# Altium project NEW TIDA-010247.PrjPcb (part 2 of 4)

## Sheet AFE and External Balancing.SchDoc
size A2; Date: Not shown in title block; ApprovedBy: Not shown in title block; CheckedBy: Not shown in title block; Author: Not shown in title block; CompanyName: Not shown in title block; Engineer: Not shown in title block; Organization: Not shown in title block; Address1: Not shown in title block; Address2: Not shown in title block; Address3: Not shown in title block; Address4: Not shown in title block; DocumentNumber: 1; Revision: Use project parameter SCH_Rev; SheetNumber: 3; SheetTotal: 10; PageSetup: Record=PageOptions¦CenterHorizontal=True¦CenterVertical=True¦PrintScale=0.69¦XCorrection=1.00¦YCorrection=1.00¦PrintKind=0¦BorderSize=5000000¦LeftOffset=0¦BottomOffset=0¦Orientation=2¦PaperLength=1000¦PaperWidth=1000¦Scale=100¦PaperSource=15¦PrintQuality=600¦MediaType=1¦DitherType=10¦PaperKind=Letter¦PrintScaleMode=1
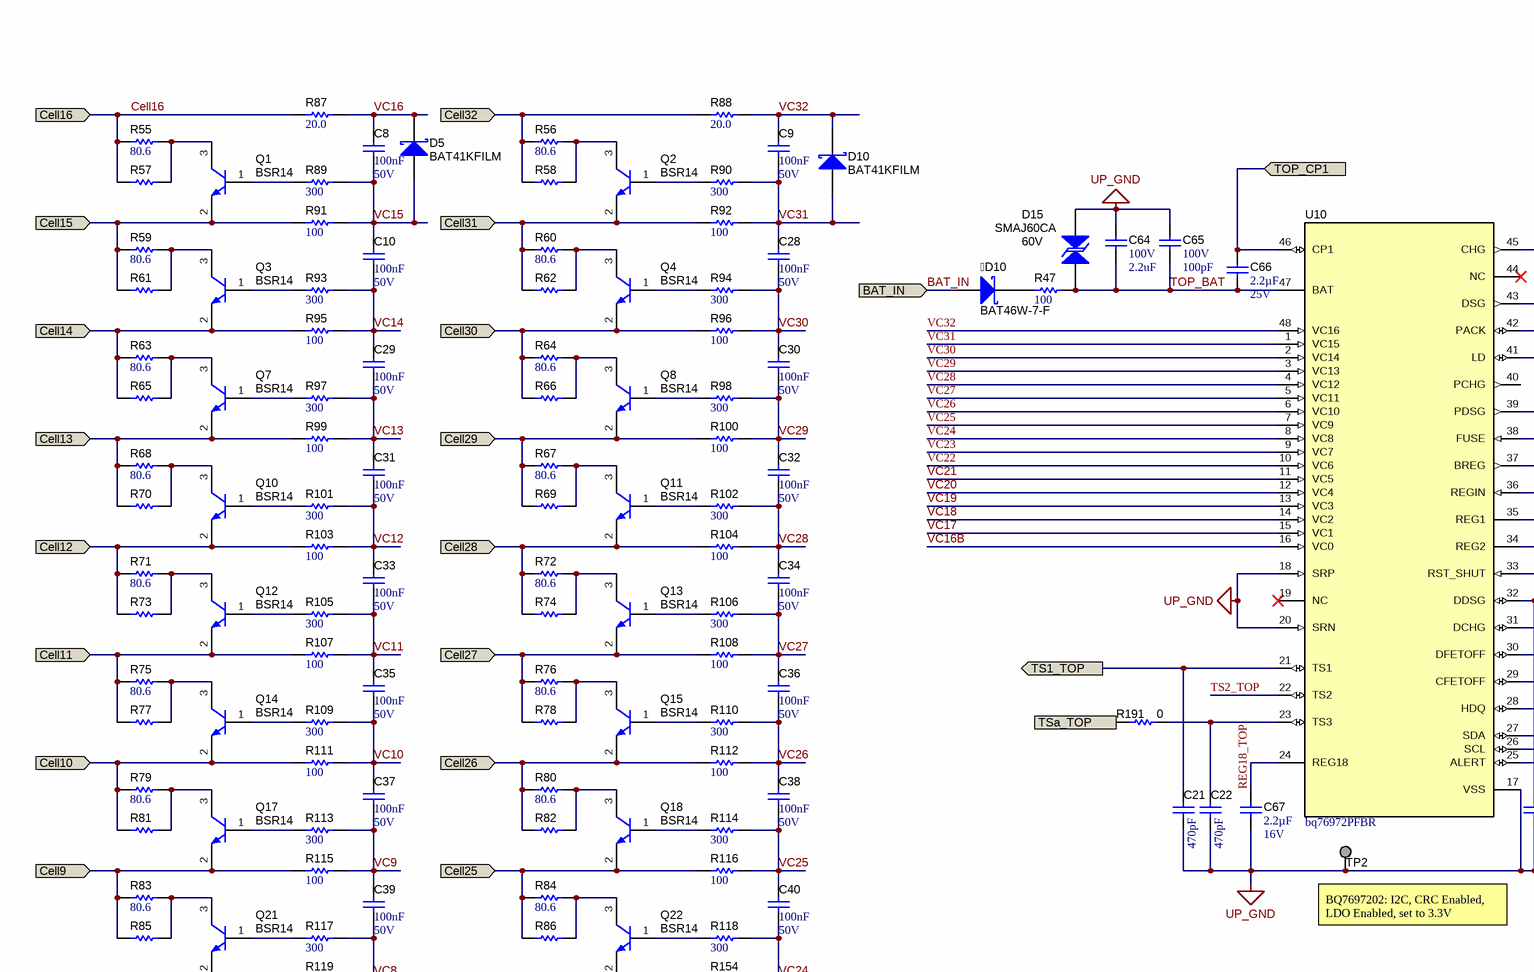
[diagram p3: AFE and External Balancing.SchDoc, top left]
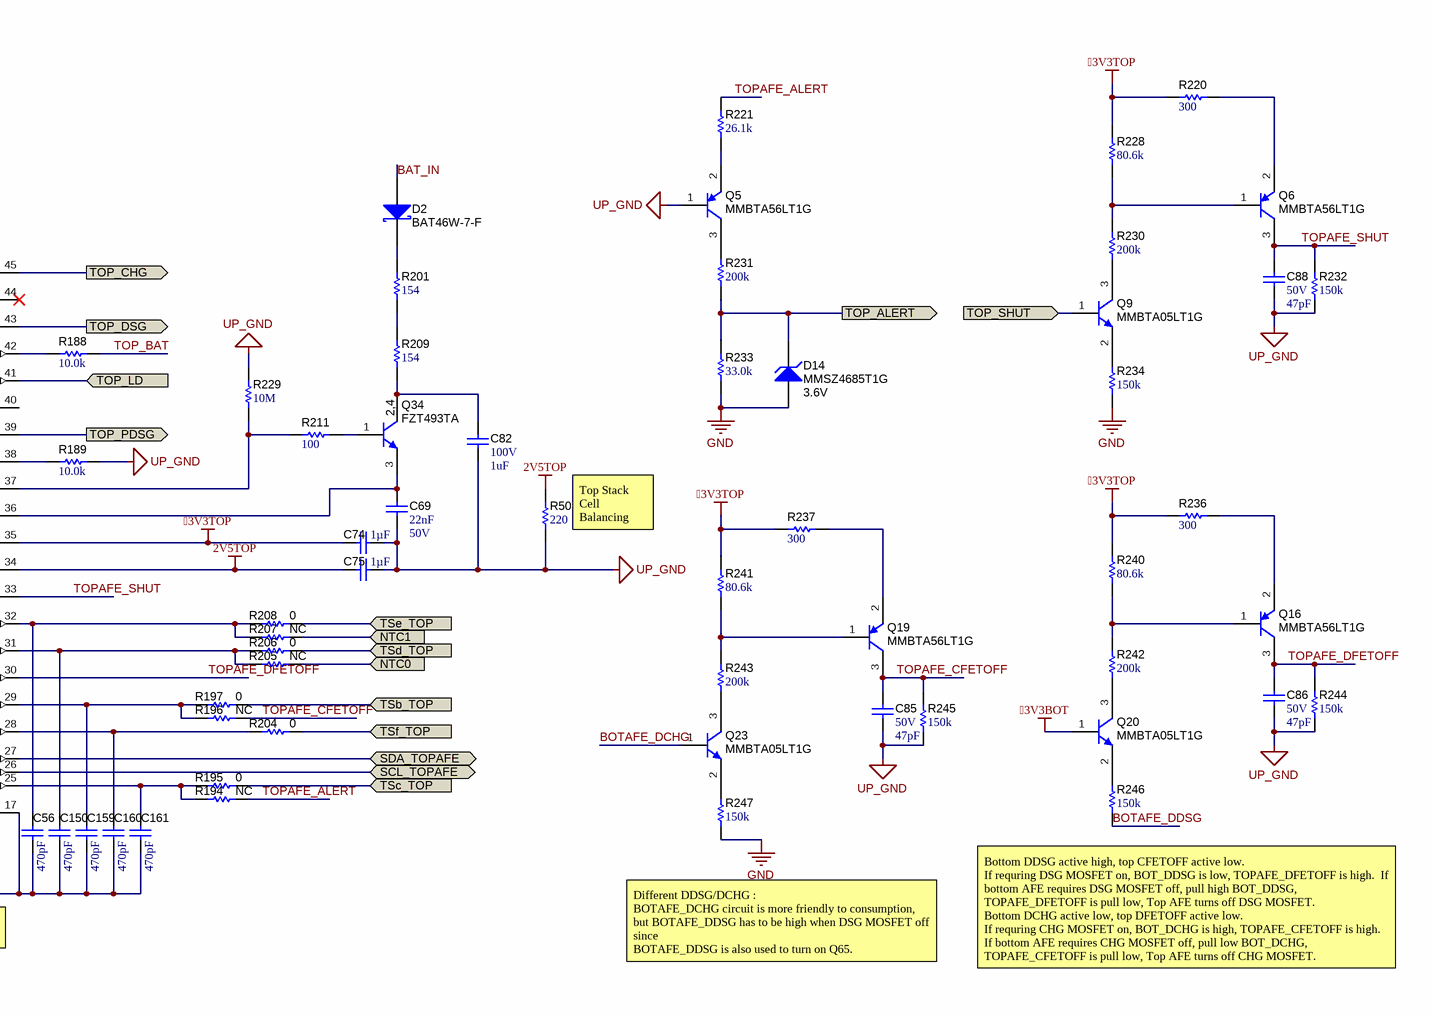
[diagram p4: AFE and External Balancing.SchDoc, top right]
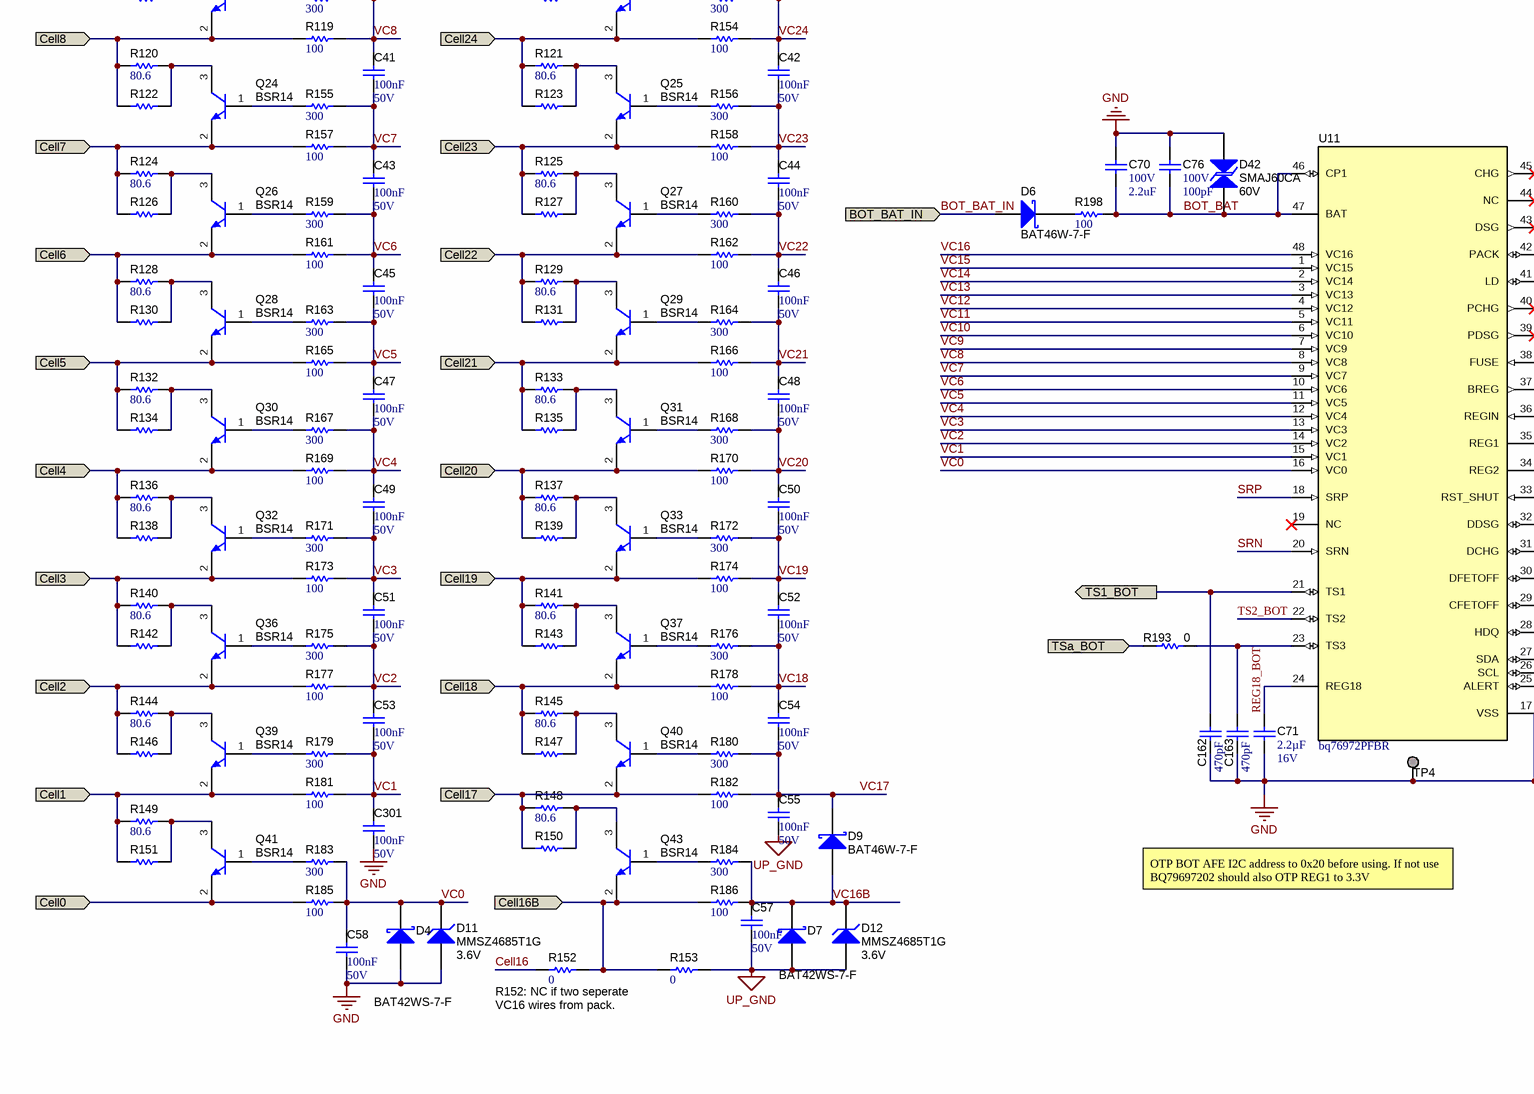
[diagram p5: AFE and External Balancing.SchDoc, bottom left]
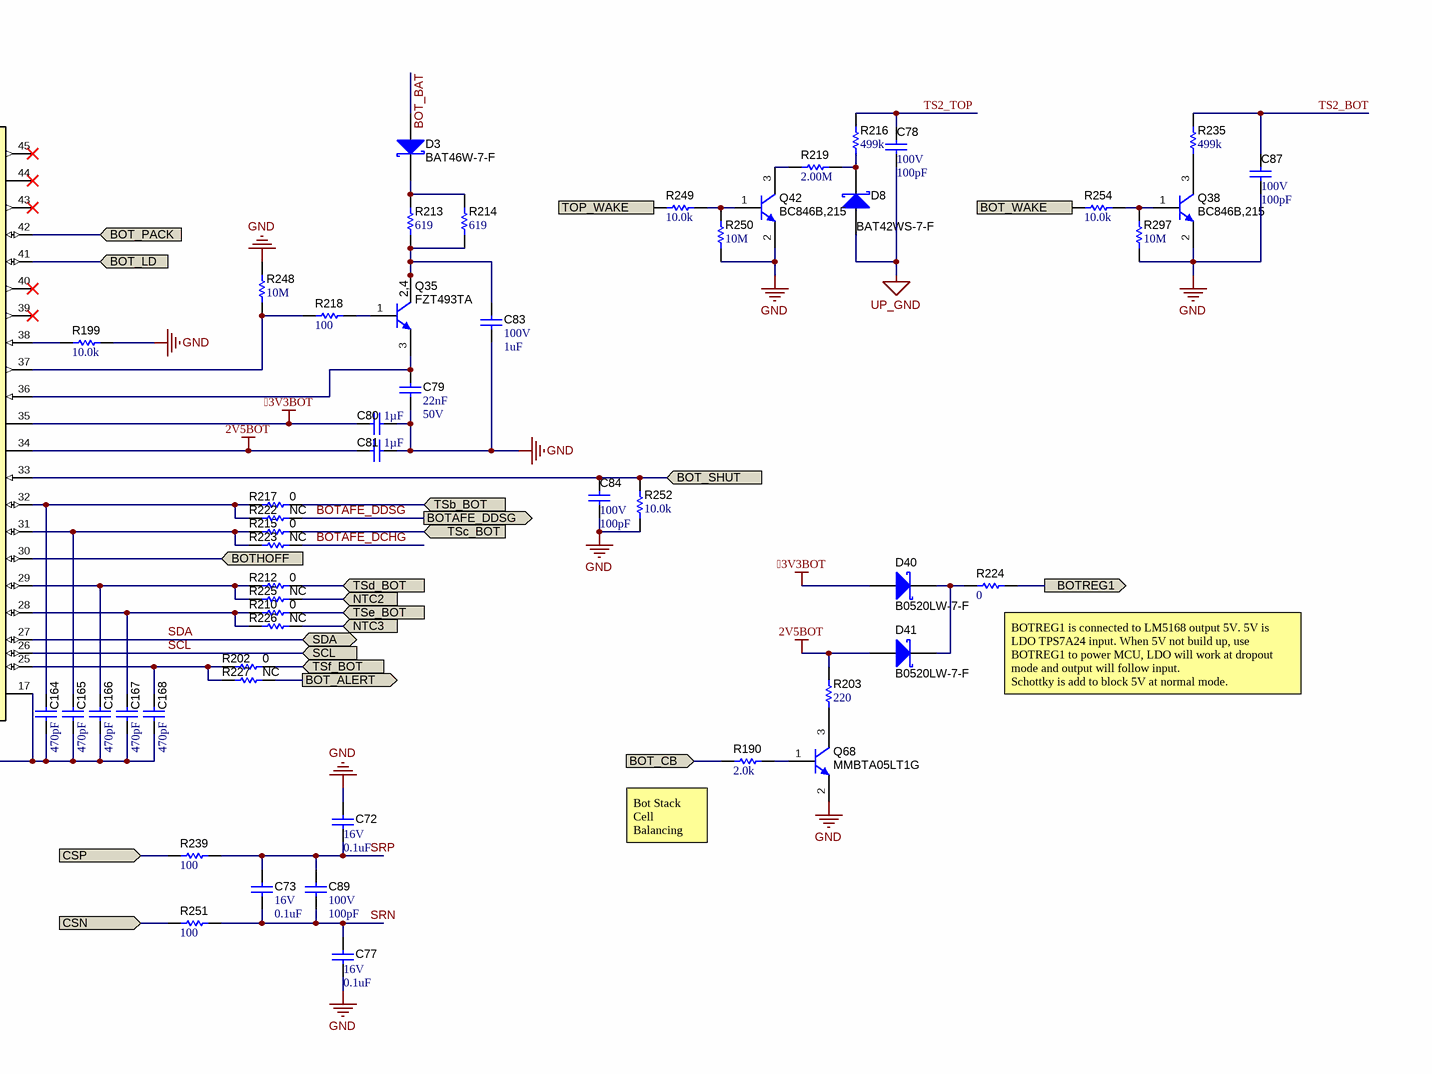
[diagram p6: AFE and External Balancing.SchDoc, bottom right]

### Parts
D10  BAT46W-7-F  [SOD-123]
C8  Cap_F: 100nF  VDC_V: 50V  [0603]  (hidden comment: GRM188R71H104KA93D)
C9  Cap_F: 100nF  VDC_V: 50V  [0603]  (hidden comment: GRM188R71H104KA93D)
C10  Cap_F: 100nF  VDC_V: 50V  [0603]  (hidden comment: GRM188R71H104KA93D)
C21  ValueDisplayed: 470pF  [0201]  (hidden comment: GRM033R71C471KA01D)  (no BOM)
C22  ValueDisplayed: 470pF  [0201]  (hidden comment: GRM033R71C471KA01D)
C28  Cap_F: 100nF  VDC_V: 50V  [0603]  (hidden comment: GRM188R71H104KA93D)
C29  Cap_F: 100nF  VDC_V: 50V  [0603]  (hidden comment: GRM188R71H104KA93D)
C30  Cap_F: 100nF  VDC_V: 50V  [0603]  (hidden comment: GRM188R71H104KA93D)
C31  Cap_F: 100nF  VDC_V: 50V  [0603]  (hidden comment: GRM188R71H104KA93D)
C32  Cap_F: 100nF  VDC_V: 50V  [0603]  (hidden comment: GRM188R71H104KA93D)
C33  Cap_F: 100nF  VDC_V: 50V  [0603]  (hidden comment: GRM188R71H104KA93D)
C34  Cap_F: 100nF  VDC_V: 50V  [0603]  (hidden comment: GRM188R71H104KA93D)
C35  Cap_F: 100nF  VDC_V: 50V  [0603]  (hidden comment: GRM188R71H104KA93D)
C36  Cap_F: 100nF  VDC_V: 50V  [0603]  (hidden comment: GRM188R71H104KA93D)
C37  Cap_F: 100nF  VDC_V: 50V  [0603]  (hidden comment: GRM188R71H104KA93D)
C38  Cap_F: 100nF  VDC_V: 50V  [0603]  (hidden comment: GRM188R71H104KA93D)
C39  Cap_F: 100nF  VDC_V: 50V  [0603]  (hidden comment: GRM188R71H104KA93D)
C40  Cap_F: 100nF  VDC_V: 50V  [0603]  (hidden comment: GRM188R71H104KA93D)
C41  Cap_F: 100nF  VDC_V: 50V  [0603]  (hidden comment: GRM188R71H104KA93D)
C42  Cap_F: 100nF  VDC_V: 50V  [0603]  (hidden comment: GRM188R71H104KA93D)
C43  Cap_F: 100nF  VDC_V: 50V  [0603]  (hidden comment: GRM188R71H104KA93D)
C44  Cap_F: 100nF  VDC_V: 50V  [0603]  (hidden comment: GRM188R71H104KA93D)
C45  Cap_F: 100nF  VDC_V: 50V  [0603]  (hidden comment: GRM188R71H104KA93D)
C46  Cap_F: 100nF  VDC_V: 50V  [0603]  (hidden comment: GRM188R71H104KA93D)
C47  Cap_F: 100nF  VDC_V: 50V  [0603]  (hidden comment: GRM188R71H104KA93D)
C48  Cap_F: 100nF  VDC_V: 50V  [0603]  (hidden comment: GRM188R71H104KA93D)
C49  Cap_F: 100nF  VDC_V: 50V  [0603]  (hidden comment: GRM188R71H104KA93D)
C50  Cap_F: 100nF  VDC_V: 50V  [0603]  (hidden comment: GRM188R71H104KA93D)
C51  Cap_F: 100nF  VDC_V: 50V  [0603]  (hidden comment: GRM188R71H104KA93D)
C52  Cap_F: 100nF  VDC_V: 50V  [0603]  (hidden comment: GRM188R71H104KA93D)
C53  Cap_F: 100nF  VDC_V: 50V  [0603]  (hidden comment: GRM188R71H104KA93D)
C54  Cap_F: 100nF  VDC_V: 50V  [0603]  (hidden comment: GRM188R71H104KA93D)
C55  Cap_F: 100nF  VDC_V: 50V  [0603]  (hidden comment: GRM188R71H104KA93D)
C56  ValueDisplayed: 470pF  [0201]  (hidden comment: GRM033R71C471KA01D)
C57  Cap_F: 100nF  VDC_V: 50V  [0603]  (hidden comment: GRM188R71H104KA93D)
C58  Cap_F: 100nF  VDC_V: 50V  [0603]  (hidden comment: GRM188R71H104KA93D)
C64  VDC_V: 100V  ValueDisplayed: 2.2uF  [1206_190]  (hidden comment: GRM31CR72A225KA73L)
C65  VDC_V: 100V  ValueDisplayed: 100pF  [0603]  (hidden comment: GRM1885C2A101JA01D)
C66  Cap_F: 2.2µF  VDC_V: 25V  [0805_HV]  (hidden comment: GRM21BR71E225KA73L)
C67  Cap_F: 2.2µF  VDC_V: 16V  [0603]  (hidden comment: EMK107BB7225MA-T)
C69  Cap_F: 22nF  VDC_V: 50V  [0603]  (hidden comment: GRM188R71H223KA01D)
C70  VDC_V: 100V  ValueDisplayed: 2.2uF  [1206_190]  (hidden comment: GRM31CR72A225KA73L)
C71  Cap_F: 2.2µF  VDC_V: 16V  [0603]  (hidden comment: EMK107BB7225MA-T)
C72  VDC_V: 16V  ValueDisplayed: 0.1uF  [0603]  (hidden comment: GRM188R61C104KA01D)
C73  VDC_V: 16V  ValueDisplayed: 0.1uF  [0603]  (hidden comment: GRM188R61C104KA01D)
C74  Cap_F: 1µF  [0603]  (hidden comment: GCM188R71C105KA64D)
C75  Cap_F: 1µF  [0603]  (hidden comment: GCM188R71C105KA64D)
C76  VDC_V: 100V  ValueDisplayed: 100pF  [0603]  (hidden comment: GRM1885C2A101JA01D)
C77  VDC_V: 16V  ValueDisplayed: 0.1uF  [0603]  (hidden comment: GRM188R61C104KA01D)
C78  VDC_V: 100V  ValueDisplayed: 100pF  [0603]  (hidden comment: GRM1885C2A101JA01D)
C79  Cap_F: 22nF  VDC_V: 50V  [0603]  (hidden comment: GRM188R71H223KA01D)
C80  Cap_F: 1µF  [0603]  (hidden comment: GCM188R71C105KA64D)
C81  Cap_F: 1µF  [0603]  (hidden comment: GCM188R71C105KA64D)
C82  VDC_V: 100V  ValueDisplayed: 1uF  [1206_180]  (hidden comment: C3216X7R2A105K160AA)
C83  VDC_V: 100V  ValueDisplayed: 1uF  [1206_180]  (hidden comment: C3216X7R2A105K160AA)
C84  VDC_V: 100V  ValueDisplayed: 100pF  [0603]  (hidden comment: GRM1885C2A101JA01D)
C85  VDC_V: 50V  ValueDisplayed: 47pF  [0603]  (hidden comment: GRM1885C1H470JA01D)
C86  VDC_V: 50V  ValueDisplayed: 47pF  [0603]  (hidden comment: GRM1885C1H470JA01D)
C87  VDC_V: 100V  ValueDisplayed: 100pF  [0603]  (hidden comment: GRM1885C2A101JA01D)
C88  VDC_V: 50V  ValueDisplayed: 47pF  [0603]  (hidden comment: GRM1885C1H470JA01D)
C89  VDC_V: 100V  ValueDisplayed: 100pF  [0603]  (hidden comment: GRM1885C2A101JA01D)
C150  ValueDisplayed: 470pF  [0201]  (hidden comment: GRM033R71C471KA01D)
C159  ValueDisplayed: 470pF  [0201]  (hidden comment: GRM033R71C471KA01D)
C160  ValueDisplayed: 470pF  [0201]  (hidden comment: GRM033R71C471KA01D)
C161  ValueDisplayed: 470pF  [0201]  (hidden comment: GRM033R71C471KA01D)
C162  ValueDisplayed: 470pF  [0201]  (hidden comment: GRM033R71C471KA01D)  (no BOM)
C163  ValueDisplayed: 470pF  [0201]  (hidden comment: GRM033R71C471KA01D)
C164  ValueDisplayed: 470pF  [0201]  (hidden comment: GRM033R71C471KA01D)
C165  ValueDisplayed: 470pF  [0201]  (hidden comment: GRM033R71C471KA01D)
C166  ValueDisplayed: 470pF  [0201]  (hidden comment: GRM033R71C471KA01D)
C167  ValueDisplayed: 470pF  [0201]  (hidden comment: GRM033R71C471KA01D)
C168  ValueDisplayed: 470pF  [0201]  (hidden comment: GRM033R71C471KA01D)
C301  Cap_F: 100nF  VDC_V: 50V  [0603]  (hidden comment: GRM188R71H104KA93D)
D2  BAT46W-7-F  [SOD-123]
D3  BAT46W-7-F  [SOD-123]
D4  BAT42WS-7-F  [SOD-323]
D5  BAT41KFILM  [SOD-523]
D6  BAT46W-7-F  [SOD-123]
D7  BAT42WS-7-F  [SOD-323]
D8  BAT42WS-7-F  [SOD-123]
D9  BAT46W-7-F  [SOD-123]
D10  BAT41KFILM  [SOD-523]
D11  MMSZ4685T1G  value 3.6V  [SOD-123]
D12  MMSZ4685T1G  value 3.6V  [SOD-123]
D14  MMSZ4685T1G  value 3.6V  [SOD-123]
D15  SMAJ60CA  value 60V  [SMA_Bi]
D40  B0520LW-7-F  [SOD-123]
D41  B0520LW-7-F  [SOD-123]  (no BOM)
D42  SMAJ60CA  value 60V  [SMA_Bi]
Q1  BSR14  [SOT-23]
Q2  BSR14  [SOT-23]
Q3  BSR14  [SOT-23]
Q4  BSR14  [SOT-23]
Q5  MMBTA56LT1G  [SOT-23]
Q6  MMBTA56LT1G  [SOT-23]
Q7  BSR14  [SOT-23]
Q8  BSR14  [SOT-23]
Q9  MMBTA05LT1G  [SOT-23]
Q10  BSR14  [SOT-23]
Q11  BSR14  [SOT-23]
Q12  BSR14  [SOT-23]
Q13  BSR14  [SOT-23]
Q14  BSR14  [SOT-23]
Q15  BSR14  [SOT-23]
Q16  MMBTA56LT1G  [SOT-23]
Q17  BSR14  [SOT-23]
Q18  BSR14  [SOT-23]
Q19  MMBTA56LT1G  [SOT-23]
Q20  MMBTA05LT1G  [SOT-23]
Q21  BSR14  [SOT-23]
Q22  BSR14  [SOT-23]
Q23  MMBTA05LT1G  [SOT-23]
Q24  BSR14  [SOT-23]
Q25  BSR14  [SOT-23]
Q26  BSR14  [SOT-23]
Q27  BSR14  [SOT-23]
Q28  BSR14  [SOT-23]
Q29  BSR14  [SOT-23]
Q30  BSR14  [SOT-23]
Q31  BSR14  [SOT-23]
Q32  BSR14  [SOT-23]
Q33  BSR14  [SOT-23]
Q34  FZT493TA  [SOT-223]
Q35  FZT493TA  [SOT-223]
Q36  BSR14  [SOT-23]
Q37  BSR14  [SOT-23]
Q38  BC846B,215  [SOT-23]
Q39  BSR14  [SOT-23]
Q40  BSR14  [SOT-23]
Q41  BSR14  [SOT-23]
Q42  BC846B,215  [SOT-23]
Q43  BSR14  [SOT-23]
Q68  MMBTA05LT1G  [SOT-23]
R47  ValueDisplayed: 100  [0603]  (hidden comment: CRCW0603100RFKEA)
R50  ValueDisplayed: 220  [1210]  (hidden comment: RC1210FR-07220RL)  (no BOM)
R55  ValueDisplayed: 80.6  [1206]  (hidden comment: CRCW120680R6FKEA)
R56  ValueDisplayed: 80.6  [1206]  (hidden comment: CRCW120680R6FKEA)
R57  CRCW120680R6FKEA  [1206]  (value not drawn)
R58  CRCW120680R6FKEA  [1206]  (value not drawn)
R59  ValueDisplayed: 80.6  [1206]  (hidden comment: CRCW120680R6FKEA)
R60  ValueDisplayed: 80.6  [1206]  (hidden comment: CRCW120680R6FKEA)
R61  CRCW120680R6FKEA  [1206]  (value not drawn)
R62  CRCW120680R6FKEA  [1206]  (value not drawn)
R63  ValueDisplayed: 80.6  [1206]  (hidden comment: CRCW120680R6FKEA)
R64  ValueDisplayed: 80.6  [1206]  (hidden comment: CRCW120680R6FKEA)
R65  CRCW120680R6FKEA  [1206]  (value not drawn)
R66  CRCW120680R6FKEA  [1206]  (value not drawn)
R67  ValueDisplayed: 80.6  [1206]  (hidden comment: CRCW120680R6FKEA)
R68  ValueDisplayed: 80.6  [1206]  (hidden comment: CRCW120680R6FKEA)
R69  CRCW120680R6FKEA  [1206]  (value not drawn)
R70  CRCW120680R6FKEA  [1206]  (value not drawn)
R71  ValueDisplayed: 80.6  [1206]  (hidden comment: CRCW120680R6FKEA)
R72  ValueDisplayed: 80.6  [1206]  (hidden comment: CRCW120680R6FKEA)
R73  CRCW120680R6FKEA  [1206]  (value not drawn)
R74  CRCW120680R6FKEA  [1206]  (value not drawn)
R75  ValueDisplayed: 80.6  [1206]  (hidden comment: CRCW120680R6FKEA)
R76  ValueDisplayed: 80.6  [1206]  (hidden comment: CRCW120680R6FKEA)
R77  CRCW120680R6FKEA  [1206]  (value not drawn)
R78  CRCW120680R6FKEA  [1206]  (value not drawn)
R79  ValueDisplayed: 80.6  [1206]  (hidden comment: CRCW120680R6FKEA)
R80  ValueDisplayed: 80.6  [1206]  (hidden comment: CRCW120680R6FKEA)
R81  CRCW120680R6FKEA  [1206]  (value not drawn)
R82  CRCW120680R6FKEA  [1206]  (value not drawn)
R83  ValueDisplayed: 80.6  [1206]  (hidden comment: CRCW120680R6FKEA)
R84  ValueDisplayed: 80.6  [1206]  (hidden comment: CRCW120680R6FKEA)
R85  CRCW120680R6FKEA  [1206]  (value not drawn)
R86  CRCW120680R6FKEA  [1206]  (value not drawn)
R87  ValueDisplayed: 20.0  [0603]  (hidden comment: CRCW060320R0FKEA)
R88  ValueDisplayed: 20.0  [0603]  (hidden comment: CRCW060320R0FKEA)
R89  ValueDisplayed: 300  [0603]  (hidden comment: CRCW0603300RJNEA)
R90  ValueDisplayed: 300  [0603]  (hidden comment: CRCW0603300RJNEA)
R91  ValueDisplayed: 100  [0603]  (hidden comment: CRCW0603100RFKEA)
R92  ValueDisplayed: 100  [0603]  (hidden comment: CRCW0603100RFKEA)
R93  ValueDisplayed: 300  [0603]  (hidden comment: CRCW0603300RJNEA)
R94  ValueDisplayed: 300  [0603]  (hidden comment: CRCW0603300RJNEA)
R95  ValueDisplayed: 100  [0603]  (hidden comment: CRCW0603100RFKEA)
R96  ValueDisplayed: 100  [0603]  (hidden comment: CRCW0603100RFKEA)
R97  ValueDisplayed: 300  [0603]  (hidden comment: CRCW0603300RJNEA)
R98  ValueDisplayed: 300  [0603]  (hidden comment: CRCW0603300RJNEA)
R99  ValueDisplayed: 100  [0603]  (hidden comment: CRCW0603100RFKEA)
R100  ValueDisplayed: 100  [0603]  (hidden comment: CRCW0603100RFKEA)
R101  ValueDisplayed: 300  [0603]  (hidden comment: CRCW0603300RJNEA)
R102  ValueDisplayed: 300  [0603]  (hidden comment: CRCW0603300RJNEA)
R103  ValueDisplayed: 100  [0603]  (hidden comment: CRCW0603100RFKEA)
R104  ValueDisplayed: 100  [0603]  (hidden comment: CRCW0603100RFKEA)
R105  ValueDisplayed: 300  [0603]  (hidden comment: CRCW0603300RJNEA)
R106  ValueDisplayed: 300  [0603]  (hidden comment: CRCW0603300RJNEA)
R107  ValueDisplayed: 100  [0603]  (hidden comment: CRCW0603100RFKEA)
R108  ValueDisplayed: 100  [0603]  (hidden comment: CRCW0603100RFKEA)
R109  ValueDisplayed: 300  [0603]  (hidden comment: CRCW0603300RJNEA)
R110  ValueDisplayed: 300  [0603]  (hidden comment: CRCW0603300RJNEA)
R111  ValueDisplayed: 100  [0603]  (hidden comment: CRCW0603100RFKEA)
R112  ValueDisplayed: 100  [0603]  (hidden comment: CRCW0603100RFKEA)
R113  ValueDisplayed: 300  [0603]  (hidden comment: CRCW0603300RJNEA)
R114  ValueDisplayed: 300  [0603]  (hidden comment: CRCW0603300RJNEA)
R115  ValueDisplayed: 100  [0603]  (hidden comment: CRCW0603100RFKEA)
R116  ValueDisplayed: 100  [0603]  (hidden comment: CRCW0603100RFKEA)
R117  ValueDisplayed: 300  [0603]  (hidden comment: CRCW0603300RJNEA)
R118  ValueDisplayed: 300  [0603]  (hidden comment: CRCW0603300RJNEA)
R119  ValueDisplayed: 100  [0603]  (hidden comment: CRCW0603100RFKEA)
R120  ValueDisplayed: 80.6  [1206]  (hidden comment: CRCW120680R6FKEA)
R121  ValueDisplayed: 80.6  [1206]  (hidden comment: CRCW120680R6FKEA)
R122  CRCW120680R6FKEA  [1206]  (value not drawn)
R123  CRCW120680R6FKEA  [1206]  (value not drawn)
R124  ValueDisplayed: 80.6  [1206]  (hidden comment: CRCW120680R6FKEA)
R125  ValueDisplayed: 80.6  [1206]  (hidden comment: CRCW120680R6FKEA)
R126  CRCW120680R6FKEA  [1206]  (value not drawn)
R127  CRCW120680R6FKEA  [1206]  (value not drawn)
R128  ValueDisplayed: 80.6  [1206]  (hidden comment: CRCW120680R6FKEA)
R129  ValueDisplayed: 80.6  [1206]  (hidden comment: CRCW120680R6FKEA)
R130  CRCW120680R6FKEA  [1206]  (value not drawn)
R131  CRCW120680R6FKEA  [1206]  (value not drawn)
R132  ValueDisplayed: 80.6  [1206]  (hidden comment: CRCW120680R6FKEA)
R133  ValueDisplayed: 80.6  [1206]  (hidden comment: CRCW120680R6FKEA)
R134  CRCW120680R6FKEA  [1206]  (value not drawn)
R135  CRCW120680R6FKEA  [1206]  (value not drawn)
R136  ValueDisplayed: 80.6  [1206]  (hidden comment: CRCW120680R6FKEA)
R137  ValueDisplayed: 80.6  [1206]  (hidden comment: CRCW120680R6FKEA)
R138  CRCW120680R6FKEA  [1206]  (value not drawn)
R139  CRCW120680R6FKEA  [1206]  (value not drawn)
R140  ValueDisplayed: 80.6  [1206]  (hidden comment: CRCW120680R6FKEA)
R141  ValueDisplayed: 80.6  [1206]  (hidden comment: CRCW120680R6FKEA)
R142  CRCW120680R6FKEA  [1206]  (value not drawn)
R143  CRCW120680R6FKEA  [1206]  (value not drawn)
R144  ValueDisplayed: 80.6  [1206]  (hidden comment: CRCW120680R6FKEA)
R145  ValueDisplayed: 80.6  [1206]  (hidden comment: CRCW120680R6FKEA)
R146  CRCW120680R6FKEA  [1206]  (value not drawn)
R147  CRCW120680R6FKEA  [1206]  (value not drawn)
R148  ValueDisplayed: 80.6  [1206]  (hidden comment: CRCW120680R6FKEA)
R149  ValueDisplayed: 80.6  [1206]  (hidden comment: CRCW120680R6FKEA)
R150  CRCW120680R6FKEA  [1206]  (value not drawn)
R151  CRCW120680R6FKEA  [1206]  (value not drawn)
R152  ValueDisplayed: 0  [0603]  (hidden comment: CRCW06030000Z0EA)
R153  ValueDisplayed: 0  [0603]  (hidden comment: CRCW06030000Z0EA)
R154  ValueDisplayed: 100  [0603]  (hidden comment: CRCW0603100RFKEA)
R155  ValueDisplayed: 300  [0603]  (hidden comment: CRCW0603300RJNEA)
R156  ValueDisplayed: 300  [0603]  (hidden comment: CRCW0603300RJNEA)
R157  ValueDisplayed: 100  [0603]  (hidden comment: CRCW0603100RFKEA)
R158  ValueDisplayed: 100  [0603]  (hidden comment: CRCW0603100RFKEA)
R159  ValueDisplayed: 300  [0603]  (hidden comment: CRCW0603300RJNEA)
R160  ValueDisplayed: 300  [0603]  (hidden comment: CRCW0603300RJNEA)
R161  ValueDisplayed: 100  [0603]  (hidden comment: CRCW0603100RFKEA)
R162  ValueDisplayed: 100  [0603]  (hidden comment: CRCW0603100RFKEA)
R163  ValueDisplayed: 300  [0603]  (hidden comment: CRCW0603300RJNEA)
R164  ValueDisplayed: 300  [0603]  (hidden comment: CRCW0603300RJNEA)
R165  ValueDisplayed: 100  [0603]  (hidden comment: CRCW0603100RFKEA)
R166  ValueDisplayed: 100  [0603]  (hidden comment: CRCW0603100RFKEA)
R167  ValueDisplayed: 300  [0603]  (hidden comment: CRCW0603300RJNEA)
R168  ValueDisplayed: 300  [0603]  (hidden comment: CRCW0603300RJNEA)
R169  ValueDisplayed: 100  [0603]  (hidden comment: CRCW0603100RFKEA)
R170  ValueDisplayed: 100  [0603]  (hidden comment: CRCW0603100RFKEA)
R171  ValueDisplayed: 300  [0603]  (hidden comment: CRCW0603300RJNEA)
R172  ValueDisplayed: 300  [0603]  (hidden comment: CRCW0603300RJNEA)
R173  ValueDisplayed: 100  [0603]  (hidden comment: CRCW0603100RFKEA)
R174  ValueDisplayed: 100  [0603]  (hidden comment: CRCW0603100RFKEA)
R175  ValueDisplayed: 300  [0603]  (hidden comment: CRCW0603300RJNEA)
R176  ValueDisplayed: 300  [0603]  (hidden comment: CRCW0603300RJNEA)
R177  ValueDisplayed: 100  [0603]  (hidden comment: CRCW0603100RFKEA)
R178  ValueDisplayed: 100  [0603]  (hidden comment: CRCW0603100RFKEA)
R179  ValueDisplayed: 300  [0603]  (hidden comment: CRCW0603300RJNEA)
R180  ValueDisplayed: 300  [0603]  (hidden comment: CRCW0603300RJNEA)
R181  ValueDisplayed: 100  [0603]  (hidden comment: CRCW0603100RFKEA)
R182  ValueDisplayed: 100  [0603]  (hidden comment: CRCW0603100RFKEA)
R183  ValueDisplayed: 300  [0603]  (hidden comment: CRCW0603300RJNEA)
R184  ValueDisplayed: 300  [0603]  (hidden comment: CRCW0603300RJNEA)
R185  ValueDisplayed: 100  [0603]  (hidden comment: CRCW0603100RFKEA)
R186  ValueDisplayed: 100  [0603]  (hidden comment: CRCW0603100RFKEA)
R188  ValueDisplayed: 10.0k  [0603]  (hidden comment: CRCW060310K0FKEA)
R189  ValueDisplayed: 10.0k  [0603]  (hidden comment: CRCW060310K0FKEA)
R190  ValueDisplayed: 2.0k  [0603]  (hidden comment: RC0603JR-072KL)
R191  ValueDisplayed: 0  [0603]  (hidden comment: CRCW04020000Z0ED)
R193  ValueDisplayed: 0  [0603]  (hidden comment: CRCW04020000Z0ED)
R194  ValueDisplayed: NC  [0603]  (hidden comment: CRCW04020000Z0ED)  (no BOM)
R195  ValueDisplayed: 0  [0603]  (hidden comment: CRCW04020000Z0ED)
R196  ValueDisplayed: NC  [0603]  (hidden comment: CRCW04020000Z0ED)  (no BOM)
R197  ValueDisplayed: 0  [0603]  (hidden comment: CRCW04020000Z0ED)
R198  ValueDisplayed: 100  [0603]  (hidden comment: CRCW0603100RFKEA)
R199  ValueDisplayed: 10.0k  [0603]  (hidden comment: CRCW060310K0FKEA)
R201  ValueDisplayed: 154  [1206]  (hidden comment: CRCW1206154RFKEA)
R202  ValueDisplayed: 0  [0603]  (hidden comment: CRCW04020000Z0ED)
R203  ValueDisplayed: 220  [1210]  (hidden comment: RC1210FR-07220RL)  (no BOM)
R204  ValueDisplayed: 0  [0603]  (hidden comment: CRCW04020000Z0ED)
R205  ValueDisplayed: NC  [0603]  (hidden comment: CRCW04020000Z0ED)  (no BOM)
R206  ValueDisplayed: 0  [0603]  (hidden comment: CRCW04020000Z0ED)
R207  ValueDisplayed: NC  [0603]  (hidden comment: CRCW04020000Z0ED)  (no BOM)
R208  ValueDisplayed: 0  [0603]  (hidden comment: CRCW04020000Z0ED)
R209  ValueDisplayed: 154  [1206]  (hidden comment: CRCW1206154RFKEA)
R210  ValueDisplayed: 0  [0603]  (hidden comment: CRCW04020000Z0ED)
R211  ValueDisplayed: 100  [0603]  (hidden comment: CRCW0603100RFKEA)
R212  ValueDisplayed: 0  [0603]  (hidden comment: CRCW04020000Z0ED)
R213  ValueDisplayed: 619  [1206]  (hidden comment: CRCW1206619RFKEA)
R214  ValueDisplayed: 619  [1206]  (hidden comment: CRCW1206619RFKEA)
R215  ValueDisplayed: 0  [0603]  (hidden comment: CRCW04020000Z0ED)
R216  ValueDisplayed: 499k  [0603]  (hidden comment: CRCW0603499KFKEA)
R217  ValueDisplayed: 0  [0603]  (hidden comment: CRCW04020000Z0ED)
R218  ValueDisplayed: 100  [0603]  (hidden comment: CRCW0603100RFKEA)
R219  ValueDisplayed: 2.00M  [0603]  (hidden comment: RC0603FR-072ML)
R220  ValueDisplayed: 300  [0603]  (hidden comment: RC0603FR-07300RL)
R221  ValueDisplayed: 26.1k  [0603]  (hidden comment: CRCW060326K1FKEA)
R222  ValueDisplayed: NC  [0603]  (hidden comment: CRCW04020000Z0ED)  (no BOM)
R223  ValueDisplayed: NC  [0603]  (hidden comment: CRCW04020000Z0ED)  (no BOM)
R224  ValueDisplayed: 0  [0402]  (hidden comment: CRCW04020000Z0ED)
R225  ValueDisplayed: NC  [0603]  (hidden comment: CRCW04020000Z0ED)  (no BOM)
R226  ValueDisplayed: NC  [0603]  (hidden comment: CRCW04020000Z0ED)  (no BOM)
R227  ValueDisplayed: NC  [0603]  (hidden comment: CRCW04020000Z0ED)  (no BOM)
R228  ValueDisplayed: 80.6k  [0603]  (hidden comment: CRCW060380K6FKEA)
R229  ValueDisplayed: 10M  [0603]  (hidden comment: CRCW060310M0JNEA)
R230  ValueDisplayed: 200k  [0603]  (hidden comment: CRCW0603200KFKEA)
R231  ValueDisplayed: 200k  [0603]  (hidden comment: CRCW0603200KFKEA)
R232  ValueDisplayed: 150k  [0603]  (hidden comment: CRCW0603150KFKEA)
R233  ValueDisplayed: 33.0k  [0603]  (hidden comment: RC0603FR-0733KL)
R234  ValueDisplayed: 150k  [0603]  (hidden comment: CRCW0603150KFKEA)
R235  ValueDisplayed: 499k  [0603]  (hidden comment: CRCW0603499KFKEA)
R236  ValueDisplayed: 300  [0603]  (hidden comment: RC0603FR-07300RL)
R237  ValueDisplayed: 300  [0603]  (hidden comment: RC0603FR-07300RL)
R239  ValueDisplayed: 100  [0603]  (hidden comment: CRCW0603100RFKEA)
R240  ValueDisplayed: 80.6k  [0603]  (hidden comment: CRCW060380K6FKEA)
R241  ValueDisplayed: 80.6k  [0603]  (hidden comment: CRCW060380K6FKEA)
R242  ValueDisplayed: 200k  [0603]  (hidden comment: CRCW0603200KFKEA)
R243  ValueDisplayed: 200k  [0603]  (hidden comment: CRCW0603200KFKEA)
R244  ValueDisplayed: 150k  [0603]  (hidden comment: CRCW0603150KFKEA)
R245  ValueDisplayed: 150k  [0603]  (hidden comment: CRCW0603150KFKEA)
R246  ValueDisplayed: 150k  [0603]  (hidden comment: CRCW0603150KFKEA)
R247  ValueDisplayed: 150k  [0603]  (hidden comment: CRCW0603150KFKEA)
R248  ValueDisplayed: 10M  [0603]  (hidden comment: CRCW060310M0JNEA)
R249  ValueDisplayed: 10.0k  [0603]  (hidden comment: CRCW060310K0FKEA)
R250  ValueDisplayed: 10M  [0603]  (hidden comment: CRCW060310M0JNEA)
R251  ValueDisplayed: 100  [0603]  (hidden comment: CRCW0603100RFKEA)
R252  ValueDisplayed: 10.0k  [0603]  (hidden comment: CRCW060310K0FKEA)
R254  ValueDisplayed: 10.0k  [0603]  (hidden comment: CRCW060310K0FKEA)
R297  ValueDisplayed: 10M  [0603]  (hidden comment: CRCW060310M0JNEA)
TP2    [TP_SM_1MM]  (value not drawn)  (no BOM)
TP4    [TP_SM_1MM]  (value not drawn)  (no BOM)
U10  PartNumber: bq76972PFBR  [PFB0048A_N]  (hidden comment: bq76952PFBR)
U11  PartNumber: bq76972PFBR  [PFB0048A_N]  (hidden comment: bq76952PFBR)

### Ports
BAT_IN (in), BOT_ALERT (out), BOT_BAT_IN (in), BOT_CB (in), BOT_LD (in), BOT_PACK (in), BOT_SHUT (in), BOT_WAKE (in), BOTAFE_DDSG (out), BOTHOFF (in), BOTREG1 (out), Cell0 (in), Cell1 (in), Cell2 (in), Cell3 (in), Cell4 (in), Cell5 (in), Cell6 (in), Cell7 (in), Cell8 (in), Cell9 (in), Cell10 (in), Cell11 (in), Cell12 (in), Cell13 (in), Cell14 (in), Cell15 (in), Cell16 (in), Cell16B (in), Cell17 (in), Cell18 (in), Cell19 (in), Cell20 (in), Cell21 (in), Cell22 (in), Cell23 (in), Cell24 (in), Cell25 (in), Cell26 (in), Cell27 (in), Cell28 (in), Cell29 (in), Cell30 (in), Cell31 (in), Cell32 (in), CSN (in), CSP (in), NTC0 (in), NTC1 (in), NTC2 (in), NTC3 (in), SCL (in), SCL_TOPAFE (bidir), SDA (bidir), SDA_TOPAFE (bidir), TOP_ALERT (out), TOP_CHG (out), TOP_CP1 (in), TOP_DSG (out), TOP_LD (in), TOP_PDSG (out), TOP_SHUT (in), TOP_WAKE (in), TS1_BOT (out), TS1_TOP (out), TSa_BOT (in), TSa_TOP (in), TSb_BOT (in), TSb_TOP (in), TSc_BOT (in), TSc_TOP (in), TSd_BOT (in), TSd_TOP (in), TSe_BOT (in), TSe_TOP (in), TSf_BOT (in), TSf_TOP (in)

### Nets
2V5BOT: C81.2 D41.2(A) R203.2 U11.34(REG2)
2V5TOP: C75.2 R50.2 U10.34(REG2)
3V3BOT: C80.2 D40.2(A) Q20.1(B) U11.35(REG1)
3V3TOP: C74.2 R220.1 R228.2 R236.1 R237.1 R240.2 R241.2 U10.35(REG1)
GND: C58.2 C70.1 C71.2 C72.2 C76.1 C77.1 C79.2 C80.1 C81.1 C83.2 C84.2 C87.2 C162.1 C163.1 C164.1 C165.1 C166.1 C167.1 C168.1 C301.2 D4.2(A) D11.2(A) D14.2(A) D42.2 Q38.2(E) Q42.2(E) Q68.2(E) R199.2 R233.1 R234.1 R247.1 R248.2 R250.1 R252.1 R297.1 TP4.1 U11.17(VSS)
UP_GND: C21.1 C22.1 C55.2 C56.1 C57.2 C64.1 C65.1 C67.2 C69.2 C74.1 C75.1 C78.2 C82.2 C85.2 C86.2 C88.2 C150.1 C159.1 C160.1 C161.1 D7.2(A) D8.2(A) D12.2(A) D15.2 Q5.1(B) R50.1 R153.2 R189.2 R229.2 R232.1 R244.1 R245.1 TP2.1 U10.17(VSS) U10.18(SRP) U10.20(SRN)
5V: R224.2 ; port BOTREG1
BAT_IN: D10.2(A) D2.2(A) ; port BAT_IN
BOT_ALERT: R227.2 ; port BOT_ALERT
BOT_BAT: C70.2 C76.2 D3.2(A) D42.1 R198.2 U11.46(CP1) U11.47(BAT)
BOT_BAT_IN: D6.2(A) ; port BOT_BAT_IN
BOT_CB: R190.1 ; port BOT_CB
BOT_LD: U11.41(LD) ; port BOT_LD
BOT_PACK: U11.42(PACK) ; port BOT_PACK
BOT_SHUT: C84.1 R252.2 U11.33(RST_SHUT) ; port BOT_SHUT
BOT_WAKE: R254.1 ; port BOT_WAKE
BOTAFE_DCHG: Q23.1(B) R223.2
BOTAFE_DDSG: R222.2 R246.1 ; port BOTAFE_DDSG
BOTHOFF: U11.30(DFETOFF) ; port BOTHOFF
Cell0: Q41.2(E) R185.1 ; port Cell0
Cell1: Q39.2(E) R149.1 R151.1 R181.1 ; port Cell1
Cell2: Q36.2(E) R144.1 R146.1 R177.1 ; port Cell2
Cell3: Q32.2(E) R140.1 R142.1 R173.1 ; port Cell3
Cell4: Q30.2(E) R136.1 R138.1 R169.1 ; port Cell4
Cell5: Q28.2(E) R132.1 R134.1 R165.1 ; port Cell5
Cell6: Q26.2(E) R128.1 R130.1 R161.1 ; port Cell6
Cell7: Q24.2(E) R124.1 R126.1 R157.1 ; port Cell7
Cell8: Q21.2(E) R119.1 R120.1 R122.1 ; port Cell8
Cell9: Q17.2(E) R83.1 R85.1 R115.1 ; port Cell9
Cell10: Q14.2(E) R79.1 R81.1 R111.1 ; port Cell10
Cell11: Q12.2(E) R75.1 R77.1 R107.1 ; port Cell11
Cell12: Q10.2(E) R71.1 R73.1 R103.1 ; port Cell12
Cell13: Q7.2(E) R68.1 R70.1 R99.1 ; port Cell13
Cell14: Q3.2(E) R63.1 R65.1 R95.1 ; port Cell14
Cell15: Q1.2(E) R59.1 R61.1 R91.1 ; port Cell15
Cell16: R55.1 R57.1 R87.1 R152.1 ; port Cell16
Cell16B: Q43.2(E) R152.2 R153.1 R186.1 ; port Cell16B
Cell17: Q40.2(E) R148.1 R150.1 R182.1 ; port Cell17
Cell18: Q37.2(E) R145.1 R147.1 R178.1 ; port Cell18
Cell19: Q33.2(E) R141.1 R143.1 R174.1 ; port Cell19
Cell20: Q31.2(E) R137.1 R139.1 R170.1 ; port Cell20
Cell21: Q29.2(E) R133.1 R135.1 R166.1 ; port Cell21
Cell22: Q27.2(E) R129.1 R131.1 R162.1 ; port Cell22
Cell23: Q25.2(E) R125.1 R127.1 R158.1 ; port Cell23
Cell24: Q22.2(E) R121.1 R123.1 R154.1 ; port Cell24
Cell25: Q18.2(E) R84.1 R86.1 R116.1 ; port Cell25
Cell26: Q15.2(E) R80.1 R82.1 R112.1 ; port Cell26
Cell27: Q13.2(E) R76.1 R78.1 R108.1 ; port Cell27
Cell28: Q11.2(E) R72.1 R74.1 R104.1 ; port Cell28
Cell29: Q8.2(E) R67.1 R69.1 R100.1 ; port Cell29
Cell30: Q4.2(E) R64.1 R66.1 R96.1 ; port Cell30
Cell31: Q2.2(E) R60.1 R62.1 R92.1 ; port Cell31
Cell32: R56.1 R58.1 R88.1 ; port Cell32
CSN: R251.1 ; port CSN
CSP: R239.1 ; port CSP
NTC0: R205.2 ; port NTC0
NTC1: R207.2 ; port NTC1
NTC2: R225.2 ; port NTC2
NTC3: R226.2 ; port NTC3
REG18_BOT: C71.1 U11.24(REG18)
REG18_TOP: C67.1 U10.24(REG18)
SCL: U11.26(SCL) ; port SCL
SCL_TOPAFE: U10.26(SCL) ; port SCL_TOPAFE
SDA: U11.27(SDA) ; port SDA
SDA_TOPAFE: U10.27(SDA) ; port SDA_TOPAFE
SRN: C73.1 C77.2 C89.2 R251.2 U11.20(SRN)
SRP: C72.1 C73.2 C89.1 R239.2 U11.18(SRP)
TOP_ALERT: D14.1(K) R231.1 R233.2 ; port TOP_ALERT
TOP_BAT: C64.2 C65.2 C66.2 D15.1 R47.2 R188.2 U10.47(BAT)
TOP_CHG: U10.45(CHG) ; port TOP_CHG
TOP_CP1: C66.1 U10.46(CP1) ; port TOP_CP1
TOP_DSG: U10.43(DSG) ; port TOP_DSG
TOP_LD: U10.41(LD) ; port TOP_LD
TOP_PDSG: U10.39(PDSG) ; port TOP_PDSG
TOP_SHUT: Q9.1(B) ; port TOP_SHUT
TOP_WAKE: R249.1 ; port TOP_WAKE
TOPAFE_ALERT: R194.2 R221.2
TOPAFE_CFETOFF: C85.1 Q19.3(C) R196.2 R245.2
TOPAFE_DFETOFF: C86.1 Q16.3(C) R244.2 U10.30(DFETOFF)
TOPAFE_SHUT: C88.1 Q6.3(C) R232.2 U10.33(RST_SHUT)
TS1_BOT: C162.2 U11.21(TS1) ; port TS1_BOT
TS1_TOP: C21.2 U10.21(TS1) ; port TS1_TOP
TS2_BOT: C87.1 R235.2 U11.22(TS2)
TS2_TOP: C78.1 R216.2 U10.22(TS2)
TSa_BOT: R193.1 ; port TSa_BOT
TSa_TOP: R191.1 ; port TSa_TOP
TSb_BOT: R217.2 ; port TSb_BOT
TSb_TOP: R197.2 ; port TSb_TOP
TSc_BOT: R215.2 ; port TSc_BOT
TSc_TOP: R195.2 ; port TSc_TOP
TSd_BOT: R212.2 ; port TSd_BOT
TSd_TOP: R206.2 ; port TSd_TOP
TSe_BOT: R210.2 ; port TSe_BOT
TSe_TOP: R208.2 ; port TSe_TOP
TSf_BOT: R202.2 ; port TSf_BOT
TSf_TOP: R204.2 ; port TSf_TOP
VC0: C58.1 D4.1(K) D11.1(K) R183.2 R185.2 U11.16(VC0)
VC1: C53.2 C301.1 R179.2 R181.2 U11.15(VC1)
VC2: C51.2 C53.1 R175.2 R177.2 U11.14(VC2)
VC3: C49.2 C51.1 R171.2 R173.2 U11.13(VC3)
VC4: C47.2 C49.1 R167.2 R169.2 U11.12(VC4)
VC5: C45.2 C47.1 R163.2 R165.2 U11.11(VC5)
VC6: C43.2 C45.1 R159.2 R161.2 U11.10(VC6)
VC7: C41.2 C43.1 R155.2 R157.2 U11.9(VC7)
VC8: C39.2 C41.1 R117.2 R119.2 U11.8(VC8)
VC9: C37.2 C39.1 R113.2 R115.2 U11.7(VC9)
VC10: C35.2 C37.1 R109.2 R111.2 U11.6(VC10)
VC11: C33.2 C35.1 R105.2 R107.2 U11.5(VC11)
VC12: C31.2 C33.1 R101.2 R103.2 U11.4(VC12)
VC13: C29.2 C31.1 R97.2 R99.2 U11.3(VC13)
VC14: C10.2 C29.1 R93.2 R95.2 U11.2(VC14)
VC15: C8.2 C10.1 D5.2(A) R89.2 R91.2 U11.1(VC15)
VC16: C8.1 D5.1(K) R87.2 U11.48(VC16)
VC16B: C57.1 D7.1(K) D9.2(A) D12.1(K) R184.2 R186.2 U10.16(VC0)
VC17: C54.2 C55.1 D9.1(K) R180.2 R182.2 U10.15(VC1)
VC18: C52.2 C54.1 R176.2 R178.2 U10.14(VC2)
VC19: C50.2 C52.1 R172.2 R174.2 U10.13(VC3)
VC20: C48.2 C50.1 R168.2 R170.2 U10.12(VC4)
VC21: C46.2 C48.1 R164.2 R166.2 U10.11(VC5)
VC22: C44.2 C46.1 R160.2 R162.2 U10.10(VC6)
VC23: C42.2 C44.1 R156.2 R158.2 U10.9(VC7)
VC24: C40.2 C42.1 R118.2 R154.2 U10.8(VC8)
VC25: C38.2 C40.1 R114.2 R116.2 U10.7(VC9)
VC26: C36.2 C38.1 R110.2 R112.2 U10.6(VC10)
VC27: C34.2 C36.1 R106.2 R108.2 U10.5(VC11)
VC28: C32.2 C34.1 R102.2 R104.2 U10.4(VC12)
VC29: C30.2 C32.1 R98.2 R100.2 U10.3(VC13)
VC30: C28.2 C30.1 R94.2 R96.2 U10.2(VC14)
VC31: C9.2 C28.1 D10.2(A) R90.2 R92.2 U10.1(VC15)
VC32: C9.1 D10.1(K) R88.2 U10.48(VC16)
NetD10_1: D10.1(K) R47.1
NetC22_2: C22.2 R191.2 U10.23(TS3)
NetC56_2: C56.2 R207.1 R208.1 U10.32(DDSG)
NetC69_1: C69.1 Q34.3(E) U10.36(REGIN)
NetC79_1: C79.1 Q35.3(E) U11.36(REGIN)
NetC82_1: C82.1 Q34.2(C) Q34.4(C) R209.1
NetC83_1: C83.1 Q35.2(C) Q35.4(C) R213.1 R214.1
NetC150_2: C150.2 R205.1 R206.1 U10.31(DCHG)
NetC159_2: C159.2 R196.1 R197.1 U10.29(CFETOFF)
NetC160_2: C160.2 R204.1 U10.28(HDQ)
NetC161_2: C161.2 R194.1 R195.1 U10.25(ALERT)
NetC163_2: C163.2 R193.2 U11.23(TS3)
NetC164_2: C164.2 R217.1 R222.1 U11.32(DDSG)
NetC165_2: C165.2 R215.1 R223.1 U11.31(DCHG)
NetC166_2: C166.2 R212.1 R225.1 U11.29(CFETOFF)
NetC167_2: C167.2 R210.1 R226.1 U11.28(HDQ)
NetC168_2: C168.2 R202.1 R227.1 U11.25(ALERT)
NetD2_1: D2.1(K) R201.2
NetD3_1: D3.1(K) R213.2 R214.2
NetD6_1: D6.1(K) R198.1
NetD8_1: D8.1(K) R216.1 R219.2
NetD40_1: D40.1(K) D41.1(K) R224.1
NetQ1_1: Q1.1(B) R89.1
NetQ1_3: Q1.3(C) R55.2 R57.2
NetQ2_1: Q2.1(B) R90.1
NetQ2_3: Q2.3(C) R56.2 R58.2
NetQ3_1: Q3.1(B) R93.1
NetQ3_3: Q3.3(C) R59.2 R61.2
NetQ4_1: Q4.1(B) R94.1
NetQ4_3: Q4.3(C) R60.2 R62.2
NetQ5_2: Q5.2(E) R221.1
NetQ5_3: Q5.3(C) R231.2
NetQ6_1: Q6.1(B) R228.1 R230.2
NetQ6_2: Q6.2(E) R220.2
NetQ7_1: Q7.1(B) R97.1
NetQ7_3: Q7.3(C) R63.2 R65.2
NetQ8_1: Q8.1(B) R98.1
NetQ8_3: Q8.3(C) R64.2 R66.2
NetQ9_2: Q9.2(E) R234.2
NetQ9_3: Q9.3(C) R230.1
NetQ10_1: Q10.1(B) R101.1
NetQ10_3: Q10.3(C) R68.2 R70.2
NetQ11_1: Q11.1(B) R102.1
NetQ11_3: Q11.3(C) R67.2 R69.2
NetQ12_1: Q12.1(B) R105.1
NetQ12_3: Q12.3(C) R71.2 R73.2
NetQ13_1: Q13.1(B) R106.1
NetQ13_3: Q13.3(C) R72.2 R74.2
NetQ14_1: Q14.1(B) R109.1
NetQ14_3: Q14.3(C) R75.2 R77.2
NetQ15_1: Q15.1(B) R110.1
NetQ15_3: Q15.3(C) R76.2 R78.2
NetQ16_1: Q16.1(B) R240.1 R242.2
NetQ16_2: Q16.2(E) R236.2
NetQ17_1: Q17.1(B) R113.1
NetQ17_3: Q17.3(C) R79.2 R81.2
NetQ18_1: Q18.1(B) R114.1
NetQ18_3: Q18.3(C) R80.2 R82.2
NetQ19_1: Q19.1(B) R241.1 R243.2
NetQ19_2: Q19.2(E) R237.2
NetQ20_2: Q20.2(E) R246.2
NetQ20_3: Q20.3(C) R242.1
NetQ21_1: Q21.1(B) R117.1
NetQ21_3: Q21.3(C) R83.2 R85.2
NetQ22_1: Q22.1(B) R118.1
NetQ22_3: Q22.3(C) R84.2 R86.2
NetQ23_2: Q23.2(E) R247.2
NetQ23_3: Q23.3(C) R243.1
NetQ24_1: Q24.1(B) R155.1
NetQ24_3: Q24.3(C) R120.2 R122.2
NetQ25_1: Q25.1(B) R156.1
NetQ25_3: Q25.3(C) R121.2 R123.2
NetQ26_1: Q26.1(B) R159.1
NetQ26_3: Q26.3(C) R124.2 R126.2
NetQ27_1: Q27.1(B) R160.1
NetQ27_3: Q27.3(C) R125.2 R127.2
NetQ28_1: Q28.1(B) R163.1
NetQ28_3: Q28.3(C) R128.2 R130.2
NetQ29_1: Q29.1(B) R164.1
NetQ29_3: Q29.3(C) R129.2 R131.2
NetQ30_1: Q30.1(B) R167.1
NetQ30_3: Q30.3(C) R132.2 R134.2
NetQ31_1: Q31.1(B) R168.1
NetQ31_3: Q31.3(C) R133.2 R135.2
NetQ32_1: Q32.1(B) R171.1
NetQ32_3: Q32.3(C) R136.2 R138.2
NetQ33_1: Q33.1(B) R172.1
NetQ33_3: Q33.3(C) R137.2 R139.2
NetQ34_1: Q34.1(B) R211.2
NetQ35_1: Q35.1(B) R218.2
NetQ36_1: Q36.1(B) R175.1
NetQ36_3: Q36.3(C) R140.2 R142.2
NetQ37_1: Q37.1(B) R176.1
NetQ37_3: Q37.3(C) R141.2 R143.2
NetQ38_1: Q38.1(B) R254.2 R297.2
NetQ38_3: Q38.3(C) R235.1
NetQ39_1: Q39.1(B) R179.1
NetQ39_3: Q39.3(C) R144.2 R146.2
NetQ40_1: Q40.1(B) R180.1
NetQ40_3: Q40.3(C) R145.2 R147.2
NetQ41_1: Q41.1(B) R183.1
NetQ41_3: Q41.3(C) R149.2 R151.2
NetQ42_1: Q42.1(B) R249.2 R250.2
NetQ42_3: Q42.3(C) R219.1
NetQ43_1: Q43.1(B) R184.1
NetQ43_3: Q43.3(C) R148.2 R150.2
NetQ68_1: Q68.1(B) R190.2
NetQ68_3: Q68.3(C) R203.1
NetR188_1: R188.1 U10.42(PACK)
NetR189_1: R189.1 U10.38(FUSE)
NetR199_1: R199.1 U11.38(FUSE)
NetR201_1: R201.1 R209.2
NetR211_1: R211.1 R229.1 U10.37(BREG)
NetR218_1: R218.1 R248.1 U11.37(BREG)

Not connected (* = marked no-connect by the designer): U10 19(NC)* 40(PCHG) 44(NC)*; U11 19(NC)* 39(PDSG)* 40(PCHG)* 43(DSG)* 44(NC)* 45(CHG)*

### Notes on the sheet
- (near R50) Top Stack Cell Balancing
- (near TP2) BQ7697202: I2C, CRC Enabled, LDO Enabled, set to 3.3V
- Different DDSG/DCHG :
  BOTAFE_DCHG circuit is more friendly to consumption, but BOTAFE_DDSG has to be high when DSG MOSFET off since
  BOTAFE_DDSG is also used to turn on Q65.
- (near R246) Bottom DDSG active high, top CFETOFF active low.
  If requring DSG MOSFET on, BOT_DDSG is low, TOPAFE_DFETOFF is high.  If bottom AFE requires DSG MOSFET off, pull high BOT_DDSG, TOPAFE_DFETOFF is pull low, Top AFE turns off DSG MOSFET.
  Bottom DCHG active low, top DFETOFF active low.
  If requring CHG MOSFET on, BOT_DCHG is high, TOPAFE_CFETOFF is high. If bottom AFE requires CHG MOSFET off, pull low BOT_DCHG, TOPAFE_CFETOFF is pull low, Top AFE turns off CHG MOSFET.
- (near R224) BOTREG1 is connected to LM5168 output 5V. 5V is LDO TPS7A24 input. When 5V not build up, use BOTREG1 to power MCU, LDO will work at dropout mode and output will follow input.
  Schottky is add to block 5V at normal mode.
- OTP BOT AFE I2C address to 0x20 before using. If not use BQ79697202 should also OTP REG1 to 3.3V
- (near R190) Bot Stack Cell Balancing
- (near R152) R152: NC if two seperate VC16 wires from pack.

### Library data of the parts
D10 D2 D3 D6 D9 = CMP-0028450-2: Diode, Schottky, 100 V, 0.15 A, SOD-123; Manufacturer: Diodes Inc.; Value: 100V; Io_A: 150mA; SizeArea_mm2: 6.545; SizeX_mm: 3.85; Value2: 0.6V; Value1: 0.15A; AEC Category: Q101; SizeZ_mm: 1.35; SizeY_mm: 1.7; Green_Lifecycle: Active; Green_REACh: Passed; SizeAreaWB_mm2: 13.095; Vf_V: 600mV
C8-C10 C28-C55 C57 C58 C301 = CMP-0007434-4: CAP, CERM, 0.1 uF, 50 V, +/- 10%, X7R, 0603; Manufacturer: MuRata; TaMin_C: -55°C; Polarized: N; SizeAreaWB_mm2: 4.68; Value1: Unknown; U/M: EA; Value: 0.1uF; TaMax_C: 125°C; SizeZ_mm: 1; SizeX_mm: 1.6; SizeY_mm: 0.8; SizeArea_mm2: 1.28; AEC Category: Q200
C21 C22 C56 C150 C159-C168 = CMP-0009758-1: CAP, CERM, 470 pF, 16 V, +/- 10%, X7R, 0201; Manufacturer: MuRata; TaMin_C: -55°C; Polarized: N; SizeAreaWB_mm2: 2.08; Value1: Unknown; U/M: EA; Value: 470pF; TaMax_C: 125°C; SizeZ_mm: 0.26; SizeX_mm: 0.6; SizeY_mm: 0.3; Value2: 16V; SizeArea_mm2: 0.18; VDC_V: ; AEC Category: Q200
C64 C70 = CMP-0008971-2: CAP, CERM, 2.2 uF, 100 V, +/- 10%, X7R, 1206_190; Manufacturer: MuRata; TaMin_C: -55°C; Polarized: N; SizeAreaWB_mm2: 10.92; Value1: Unknown; U/M: EA; Value: 2.2uF; TaMax_C: 125°C; SizeZ_mm: 1.9; SizeX_mm: 3.2; SizeY_mm: 1.6; Cap_Case: 1206; SizeArea_mm2: 5.12; Cap_F: 2.2µF; AEC Category: Q200
C65 C76 C78 C84 C87 C89 = CMP-0007237-4: CAP, CERM, 100 pF, 100 V, +/- 5%, C0G/NP0, 0603; Manufacturer: MuRata; TaMin_C: -55°C; Polarized: N; SizeAreaWB_mm2: 4.68; Value1: Unknown; U/M: EA; Value: 100pF; TaMax_C: 125°C; SizeZ_mm: 1; SizeX_mm: 1.6; SizeY_mm: 0.8; SizeArea_mm2: 1.28; AEC Category: Q200
C66 = CMP-0008342-1: CAP, CERM, 2.2 uF, 25 V, +/- 10%, X7R, 0805; Manufacturer: MuRata; TaMin_C: -55°C; ESR_ohm: 5m; Polarized: N; SizeAreaWB_mm2: 6.75; Value1: 0.005 ohm; U/M: EA; Value: 2.2uF; TaMax_C: 125°C; SizeZ_mm: 1.45; SizeX_mm: 2; SizeY_mm: 1.25; Cap_Case: 0805; SizeArea_mm2: 2.5; AEC Category: Q200
C67 C71 = CMP-0064934-1: CAP, CERM, 2.2 uF, 16 V,+/- 10%, X7R, 0603; Manufacturer: Taiyo Yuden; TaMin_C: -55°C; Polarized: N; SizeAreaWB_mm2: 4.68; Value1: Unknown; U/M: EA; Value: 2.2uF; TaMax_C: 125°C; SizeZ_mm: 1; SizeX_mm: 1.6; SizeY_mm: 0.8; SizeArea_mm2: 1.28; AEC Category: Q200
C69 C79 = CMP-0007444-2: CAP, CERM, 0.022 uF, 50 V, +/- 10%, X7R, 0603; Manufacturer: MuRata; TaMin_C: -55°C; Polarized: N; SizeAreaWB_mm2: 4.68; Value1: Unknown; U/M: EA; TaMax_C: 125°C; SizeZ_mm: 1; SizeX_mm: 1.6; SizeY_mm: 0.8; SizeArea_mm2: 1.28; AEC Category: Q200
C72 C73 C77 = CMP-0007334-3: CAP, CERM, 0.1 uF, 16 V, +/- 10%, X5R, 0603; Manufacturer: MuRata; TaMin_C: -55°C; Polarized: N; SizeAreaWB_mm2: 4.68; Value1: Unknown; U/M: EA; Value: 0.1uF; TaMax_C: 85°C; SizeZ_mm: 1; SizeX_mm: 1.6; SizeY_mm: 0.8; SizeArea_mm2: 1.28; Cap_F: 100nF; AEC Category: Q200
C74 C75 C80 C81 = CMP-0007136-1: CAP, CERM, 1 uF, 16 V, +/- 10%, X7R, AEC-Q200 Grade 1, 0603; Manufacturer: MuRata; TaMin_C: -55°C; Polarized: N; SizeAreaWB_mm2: 4.68; Value1: Unknown; U/M: EA; Value: 1uF; TaMax_C: 125°C; SizeZ_mm: 1; SizeX_mm: 1.6; SizeY_mm: 0.8; Value2: 16V; SizeArea_mm2: 1.28; AEC Qualified: Y; AEC Category: Q200
C82 C83 = CMP-0008710-1: CAP, CERM, 1 uF, 100 V, +/- 10%, X7R, 1206; Manufacturer: TDK; TaMin_C: -55°C; ESR_ohm: 4.575m; Polarized: N; SizeAreaWB_mm2: 10.92; Value1: 0.004575 ohm; U/M: EA; Value: 1uF; TaMax_C: 125°C; SizeZ_mm: 1.8; SizeX_mm: 3.2; SizeY_mm: 1.6; SizeArea_mm2: 5.12; Cap_F: 1µF; IRMS_A: 3.3964A; AEC Category: Q200
C85 C86 C88 = CMP-0007220-3: CAP, CERM, 47 pF, 50 V, +/- 5%, C0G/NP0, 0603; Manufacturer: MuRata; TaMin_C: -55°C; Polarized: N; SizeAreaWB_mm2: 4.68; Value1: Unknown; U/M: EA; Value: 47pF; TaMax_C: 125°C; SizeZ_mm: 1; SizeX_mm: 1.6; SizeY_mm: 0.8; SizeArea_mm2: 1.28; AEC Category: Q200
D4 D7 = CMP-0028447-2: Diode, Schottky, 30 V, 0.2 A, SOD-323; Manufacturer: Diodes Inc.; SizeZ_mm: 1; AEC Category: Q101; Green_REACh: Incomplete; Green_Lifecycle: Not Set; Vr_V: 30V; Vf_V: 1V; Io_A: 200mA; SizeY_mm: 1.35; Value1: 0.2A; Value: 30V; SizeArea_mm2: 3.645; SizeX_mm: 2.7; SizeAreaWB_mm2: 8.695
D5 D10 = CMP-0028894-3: Diode, Schottky, 100 V, 0.2 A, SOD-523; Manufacturer: STMicroelectronics; SizeZ_mm: 0.65; Vf_V: 1V; SizeArea_mm2: 1.53; AEC Qualified: N; TJmax_C: 150°C; SizeX_mm: 1.7; SizeY_mm: 0.9; Value1: 0.2A; Green_REACh: Incomplete; SizeAreaWB_mm2: 5.13; Value: 100V; Green_Lifecycle: Not Set; Io_A: 200mA; AEC Category: Q101
D8 = BAT42WS-7-F: Diode, Schottky, 30 V, 0.2 A, SOD-323; Manufacturer: Diodes Inc.; U/M: EA; Vf_V: 1; Value: 30V; Value1: 0.2A; Value2: 1V; Io_A: 0.2; Vr_V: 30; SizeAreaWB_mm2: 8.695; SizeArea_mm2: 3.645; SizeX_mm: 2.7; SizeY_mm: 1.35; AEC Category: Q101; Green_Lifecycle: Not Set; Green_REACh: Incomplete
D11 D12 D14 = CMP-0005782-3: Diode, Zener, 3.6 V, 500 mW, SOD-123; Manufacturer: ON Semiconductor; Value1: 0.5W; SizeZ_mm: 1.35; Power_W: 500mW; SizeX_mm: 3.85; SizeY_mm: 1.7; SizeAreaWB_mm2: 13.095; RJA_CperW: 340; AEC Category: Q101; SizeArea_mm2: 6.545
D15 D42 = CMP-0085025-1: Diode, TVS, Bi, 60 V, 96.8 Vc, 400 W, 4.1 A, SMA (non-polarized); Manufacturer: Good-Ark Semiconductor; SizeAreaWB_mm2: 32.368125; AEC Category: Q101; SizeY_mm: 2.575; Vbr_Max: 73.7V; Value1: 96.8V; SizeX_mm: 5.075; SizeZ_mm: 2.65; Ipp: 4.1A; Vbr_Min: 66.7V; AEC Qualified: N; RJA_CperW: 120; SizeArea_mm2: 13.068125; Ppk: 400W
D40 D41 = CMP-0080707-2: Diode, Schottky, 20 V, 0.5 A, SOD-123; Manufacturer: Diodes Inc.; SizeY_mm: 1.7; Vf_V: 330mV; Vr_V: 20V; SizeZ_mm: 1.35; AEC Qualified: N; SizeAreaWB_mm2: 13.095; AEC Category: Q101; Value: 20V; Value1: 0.5A; Io_A: 500mA; Value2: 0.33V; TJmax_C: 125°C; SizeArea_mm2: 6.545; SizeX_mm: 3.85
Q1-Q4 Q7 Q8 Q10-Q15 Q17 Q18 Q21 Q22 Q24-Q33 Q36 Q37 Q39-Q41 Q43 = CMP-0000433-1: Transistor, NPN, 40 V, 0.8 A, SOT-23; Manufacturer: NXP Semiconductor; TaMax_C: 150°C; Value2: 300; Value1: 0.8 A; Vcesat1_V: 300mV; SizeX_mm: 2.5; SizeY_mm: 3; TaMin_C: -65°C; IcRated_A: 800mA; CompType: BJT; SizeZ_mm: 1.1; Value: 40 V; SizeArea_mm2: 7.5; NPN: 1; Vceo_V: 40V; PNP: 0; AEC Category: Q101; SizeAreaWB_mm2: 14; U/M: EA
Q5 Q6 Q16 Q19 = CMP-0000338-1: Transistor, PNP, 80 V, 0.5 A, SOT-23; Manufacturer: ON Semiconductor; TaMax_C: 150°C; Value1: 0.5 A; Vcesat1_V: 250mV; SizeX_mm: 2.5; SizeY_mm: 3; TaMin_C: -55°C; IcRated_A: 500mA; CompType: BJT; SizeZ_mm: 1.1; Value: 80 V; SizeArea_mm2: 7.5; NPN: 0; Vceo_V: 80V; PNP: 1; AEC Category: Q101; SizeAreaWB_mm2: 14; U/M: EA
Q9 Q20 Q23 = CMP-0000488-1: Transistor, NPN, 60 V, 0.5 A, AEC-Q101, SOT-23; Manufacturer: ON Semiconductor; TaMax_C: 150°C; Value1: 0.5 A; Vcesat1_V: 250mV; SizeX_mm: 2.5; SizeY_mm: 3; TaMin_C: -55°C; IcRated_A: 500mA; CompType: BJT; SizeZ_mm: 1.1; AEC Qualified: Y; Value: 60 V; SizeArea_mm2: 7.5; NPN: 1; Vceo_V: 60V; PNP: 0; AEC Category: Q101; SizeAreaWB_mm2: 14; U/M: EA
Q34 Q35 = CMP-0000473-2: Transistor, NPN, 100 V, 1 A, AEC-Q101, SOT-223; Manufacturer: Diodes Inc.; TaMax_C: 150°C; Value2: 300; Value1: 1 A; Vcesat1_V: 300mV; SizeX_mm: 6.5; SizeY_mm: 7; TaMin_C: -55°C; IcRated_A: 1A; CompType: BJT; SizeZ_mm: 1.6; AEC Qualified: Y; Value: 100 V; SizeArea_mm2: 45.5; NPN: 1; Vceo_V: 100V; PNP: 0; AEC Category: Q101; SizeAreaWB_mm2: 76.5; U/M: EA
Q38 Q42 = CMP-0000487-2: Transistor, NPN, 65 V, 0.1 A, SOT-23; Manufacturer: NXP Semiconductor; TaMax_C: 150°C; Value2: 450; Value1: 0.1 A; Vcesat1_V: 90mV; SizeX_mm: 2.5; SizeY_mm: 3; TaMin_C: -65°C; IcRated_A: 100mA; CompType: BJT; SizeZ_mm: 1.1; AEC Qualified: N; Value: 65 V; SizeArea_mm2: 7.5; NPN: 1; Vceo_V: 65V; PNP: 0; AEC Category: Q101; SizeAreaWB_mm2: 14; U/M: EA
Q68 = CMP-0000488-2: Transistor, NPN, 60 V, 0.5 A, AEC-Q101, SOT-23; Manufacturer: ON Semiconductor; TaMax_C: 150°C; Value1: 0.5 A; Vcesat1_V: 2.5dV; SizeX_mm: 2.5; SizeY_mm: 3; TaMin_C: -55°C; IcRated_A: 5dA; CompType: BJT; SizeZ_mm: 1.1; AEC Qualified: Y; Value: 60 V; SizeArea_mm2: 7.5; NPN: 1; Vceo_V: 60V; PNP: 0; AEC Category: Q101; SizeAreaWB_mm2: 14; U/M: EA
R47 R91 R92 R95 R96 R99 R100 R103 R104 R107 R108 R111 R112 R115 R116 R119 R154 R157 R158 R161 R162 R165 R166 R169 R170 R173 R174 R177 R178 R181 R182 R185 R186 R198 R211 R218 R239 R251 = CMP-0021991-2: RES, 100, 1%, 0.1 W, 0603; Manufacturer: Vishay-Dale; Power_W: 100mW; TempCo: 100 ppm/C; Value_Code: 100R; U/M: EA; Value: 100; EIA_Code: E96; SizeX_mm: 1.6; SizeY_mm: 0.8; SizeZ_mm: 1; Value2: 0.1W; SizeArea_mm2: 1.28; VDC_V: 75V; AEC Category: Q200
R50 R203 = CMP-0082952-1: RES, 220, 1%, 0.5 W, 1210; Manufacturer: Yageo; Power_W: 500mW; TempCo: 100 ppm/C; SizeAreaWB_mm2: 14.7; Value_Code: 220R; Value: 220; SizeX_mm: 3.2; SizeY_mm: 2.5; SizeZ_mm: 1.35; Value2: 0.5W; SizeArea_mm2: 8; AEC Qualified: N; VDC_V: 200V; AEC Category: Q200
R55-R86 R120-R151 = CMP-0017186-1: RES, 80.6, 1%, 0.25 W, 1206; Manufacturer: Vishay-Dale; Power_W: 250mW; TempCo: 100 ppm/C; Value_Code: 80R6; U/M: EA; Value: 80.6; EIA_Code: E96; SizeX_mm: 3.2; SizeY_mm: 1.6; SizeZ_mm: 1.35; Value2: 0.25W; SizeArea_mm2: 5.12; VDC_V: 200V; AEC Category: Q200
R87 R88 = CMP-0022206-2: RES, 20.0, 1%, 0.1 W, 0603; Manufacturer: Vishay-Dale; Power_W: 100mW; TempCo: 100 ppm/C; Value_Code: 20R0; U/M: EA; Value: 20.0; EIA_Code: E96; Res_ohm: 20; SizeX_mm: 1.6; SizeY_mm: 0.8; SizeZ_mm: 1; Value2: 0.1W; SizeArea_mm2: 1.28; VDC_V: 75V; AEC Category: Q200
R89 R90 R93 R94 R97 R98 R101 R102 R105 R106 R109 R110 R113 R114 R117 R118 R155 R156 R159 R160 R163 R164 R167 R168 R171 R172 R175 R176 R179 R180 R183 R184 = CMP-0025781-3: RES, 300, 5%, 0.1 W, 0603; Manufacturer: Vishay-Dale; Power_W: 100mW; TempCo: 200 ppm/C; Value_Code: 300R; U/M: EA; Value: 300; EIA_Code: E24; SizeX_mm: 1.6; SizeY_mm: 0.8; SizeZ_mm: 1; Value2: 0.1W; SizeArea_mm2: 1.28; VDC_V: 75V; AEC Category: Q200
R152 R153 = CMP-0025697-4: RES, 0, 5%, 0.1 W, AEC-Q200 Grade 0, 0603; Manufacturer: Vishay-Dale; Power_W: 100mW; TempCo: 200 ppm/C; Value_Code: 0000; Value: 0; EIA_Code: E24; SizeX_mm: 1.6; SizeY_mm: 0.8; SizeZ_mm: 1; Value2: 0.1W; SizeArea_mm2: 1.28; AEC Qualified: Y; VDC_V: 75V; AEC Category: Q200
R188 R189 R199 R249 R252 R254 = CMP-0021998-4: RES, 10.0 k, 1%, 0.1 W, AEC-Q200 Grade 0, 0603; Manufacturer: Vishay-Dale; Power_W: 100mW; TempCo: 100 ppm/C; Value_Code: 10k0; Value: 10.0k; EIA_Code: E96; Res_ohm: 10k; SizeX_mm: 1.6; SizeY_mm: 0.8; SizeZ_mm: 1; Value2: 0.1W; SizeArea_mm2: 1.28; AEC Qualified: Y; VDC_V: 75V; AEC Category: Q200; AEC Grade: 0
R190 = CMP-0025909-5: RES, 2.0 k, 5%, 0.1 W, 0603; Manufacturer: Yageo; Power_W: 100mW; TempCo: 100 ppm/C; Value_Code: 2k00; Value: 2.0k; EIA_Code: E24; Res_ohm: 2k; SizeX_mm: 1.6; SizeY_mm: 0.8; SizeZ_mm: 1; Value2: 0.1W; SizeArea_mm2: 1.28; AEC Qualified: N; VDC_V: 75V; AEC Category: Q200; SizeAreaWB_mm2: 4.68
R191 R193-R197 R202 R204-R208 R210 R212 R215 R217 R222 R223 R225-R227 = CRCW04020000Z0ED: RES, 0, 5%, 0.063 W, 0402; Manufacturer: Vishay-Dale; CompType: Resistor; Value: 0; Value_Code: 0000; Tolerance_%: 5; Power_W: 0.063; Value2: 0.063W; VDC_V: 50; TempCo: 200 ppm/C; SizeArea_mm2: 0.5; SizeX_mm: 1; SizeZ_mm: 0.6; EIA_Code: E24; U/M: EA; AEC Category: Q200; Green_Lifecycle: Active; Green_REACh: Passed
R201 R209 = CMP-0016642-2: RES, 154, 1%, 0.25 W, 1206; Manufacturer: Vishay-Dale; Power_W: 250mW; TempCo: 100 ppm/C; Value_Code: 154R; U/M: EA; Value: 154; EIA_Code: E96; SizeX_mm: 3.2; SizeY_mm: 1.6; SizeZ_mm: 1.35; Value2: 0.25W; SizeArea_mm2: 5.12; VDC_V: 200V; AEC Category: Q200
R213 R214 = CMP-0017104-3: RES, 619, 1%, 0.25 W, AEC-Q200 Grade 0, 1206; Manufacturer: Vishay-Dale; Power_W: 250mW; TempCo: 100 ppm/C; Value_Code: 619R; Value: 619; EIA_Code: E96; SizeX_mm: 3.2; SizeY_mm: 1.6; SizeZ_mm: 1.35; Value2: 0.25W; SizeArea_mm2: 5.12; AEC Qualified: Y; VDC_V: 200V; AEC Category: Q200; AEC Grade: 0
R216 R235 = CMP-0022445-3: RES, 499 k, 1%, 0.1 W, 0603; Manufacturer: Vishay-Dale; Power_W: 100mW; TempCo: 100 ppm/C; U/M: EA; Value: 499k; EIA_Code: E96; SizeX_mm: 1.6; SizeY_mm: 0.8; SizeZ_mm: 1; Value2: 0.1W; SizeArea_mm2: 1.28; VDC_V: 75V; AEC Category: Q200
R219 = CMP-0023004-4: RES, 2.00 M, 1%, 0.1 W, 0603; Manufacturer: Yageo; Power_W: 100mW; TempCo: 100 ppm/C; Value_Code: 2M00; Value: 2.00Meg; EIA_Code: E96; Res_ohm: 2M; SizeX_mm: 1.6; SizeY_mm: 0.8; SizeZ_mm: 1; Value2: 0.1W; SizeArea_mm2: 1.28; AEC Qualified: N; VDC_V: 75V; AEC Category: Q200; SizeAreaWB_mm2: 4.68
R220 R236 R237 = CMP-0023013-5: RES, 300, 1%, 0.1 W, 0603; Manufacturer: Yageo; Power_W: 100mW; TempCo: 100 ppm/C; Value_Code: 300R; Value: 300; SizeX_mm: 1.6; SizeY_mm: 0.8; SizeZ_mm: 1; Value2: 0.1W; SizeArea_mm2: 1.28; AEC Qualified: N; VDC_V: 75V; AEC Category: Q200; SizeAreaWB_mm2: 4.68
R221 = CMP-0022248-4: RES, 26.1 k, 1%, 0.1 W, AEC-Q200 Grade 0, 0603; Manufacturer: Vishay-Dale; Power_W: 100mW; TempCo: 100 ppm/C; Value_Code: 26k1; Value: 26.1k; EIA_Code: E96; SizeX_mm: 1.6; SizeY_mm: 0.8; SizeZ_mm: 1; Value2: 0.1W; SizeArea_mm2: 1.28; AEC Qualified: Y; VDC_V: 75V; AEC Category: Q200; AEC Grade: 0
R224 = CMP-0026822-3: RES, 0, 5%, 0.063 W, AEC-Q200 Grade 0, 0402; Manufacturer: Vishay-Dale; Power_W: 63mW; TempCo: 200 ppm/C; Value_Code: 0000; Value: 0; EIA_Code: E24; SizeX_mm: 1; SizeY_mm: 0.5; SizeZ_mm: 0.6; Value2: 0.063W; AEC Qualified: Y; VDC_V: 50V; AEC Category: Q200
R228 R240 R241 = CMP-0022616-2: RES, 80.6 k, 1%, 0.1 W, 0603; Manufacturer: Vishay-Dale; Power_W: 100mW; TempCo: 100 ppm/C; Value_Code: 80k6; U/M: EA; Value: 80.6k; EIA_Code: E96; SizeX_mm: 1.6; SizeY_mm: 0.8; SizeZ_mm: 1; Value2: 0.1W; SizeArea_mm2: 1.28; VDC_V: 75V; AEC Category: Q200
R229 R248 R250 R297 = CMP-0025702-4: RES, 10 M, 5%, 0.1 W, AEC-Q200 Grade 0, 0603; Manufacturer: Vishay-Dale; Power_W: 100mW; TempCo: 200 ppm/C; Value_Code: 10M0; Value: 10Meg; EIA_Code: E24; SizeX_mm: 1.6; SizeY_mm: 0.8; SizeZ_mm: 1; Value2: 0.1W; SizeArea_mm2: 1.28; AEC Qualified: Y; VDC_V: 75V; AEC Category: Q200; AEC Grade: 0
R230 R231 R242 R243 = CMP-0022200-2: RES, 200 k, 1%, 0.1 W, 0603; Manufacturer: Vishay-Dale; Power_W: 100mW; TempCo: 100 ppm/C; U/M: EA; Value: 200k; EIA_Code: E96; SizeX_mm: 1.6; SizeY_mm: 0.8; SizeZ_mm: 1; Value2: 0.1W; SizeArea_mm2: 1.28; VDC_V: 75V; AEC Category: Q200
R232 R234 R244-R247 = CMP-0022060-3: RES, 150 k, 1%, 0.1 W, 0603; Manufacturer: Vishay-Dale; Power_W: 100mW; TempCo: 100 ppm/C; U/M: EA; Value: 150k; EIA_Code: E96; SizeX_mm: 1.6; SizeY_mm: 0.8; SizeZ_mm: 1; Value2: 0.1W; SizeArea_mm2: 1.28; VDC_V: 75V; AEC Category: Q200
R233 = CMP-0023037-5: RES, 33.0 k, 1%, 0.1 W, 0603; Manufacturer: Yageo; Power_W: 100mW; TempCo: 100 ppm/C; Value_Code: 33k0; Value: 33.0k; Res_ohm: 33k; SizeX_mm: 1.6; SizeY_mm: 0.8; SizeZ_mm: 1; Value2: 0.1W; SizeArea_mm2: 1.28; AEC Qualified: N; VDC_V: 75V; AEC Category: Q200; SizeAreaWB_mm2: 4.68
TP2 TP4 = CMP-0003825-1: 1mm Test Point, SMT; Manufacturer: Any
U10 U11 = CMP-0084230-1: Multicell Battery Monitor and Protection Family, PFB0048A (TQFP-48); Alternate PartNumber: bq76952PFBT; Alternate Manufacturer: Texas Instruments; SizeAreaWB_mm2: 121; SizeZ_mm: 1.2; SizeX_mm: 9; SizeArea_mm2: 81; CompType: IC; AEC Qualified: N; AEC Category: Q200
